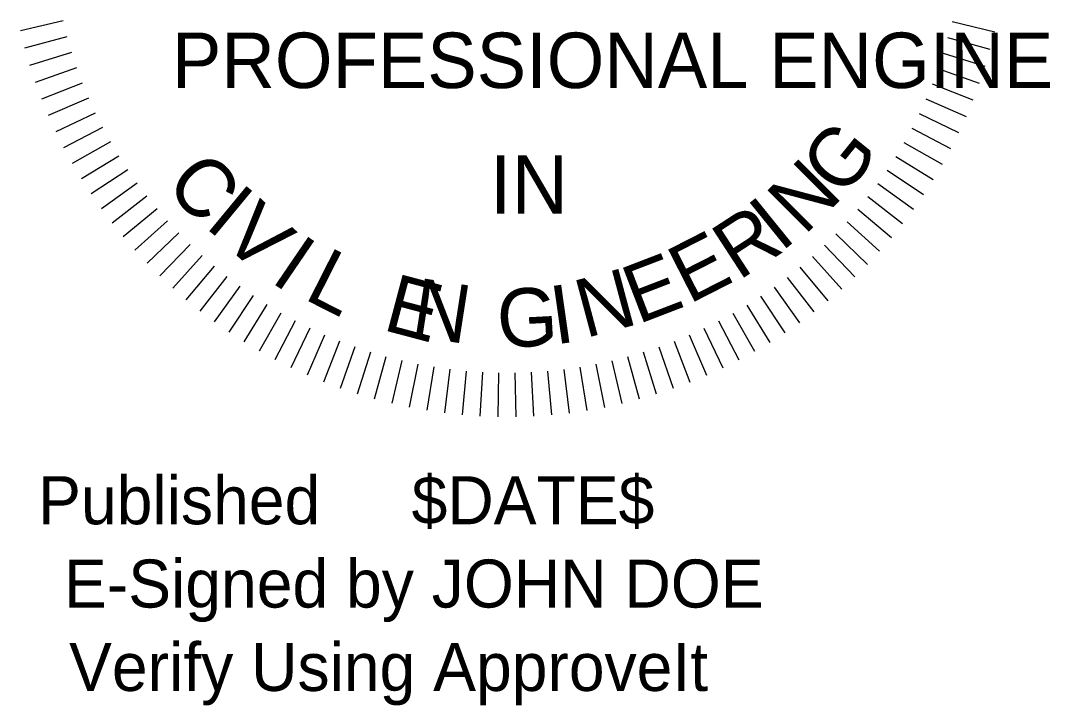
# Model space of a CAD drawing. Extents: x 0.19 to 2.82, y 0.04 to 1.79.
# Drawn here: x 2.2553 to 2.3944, y 0.7604 to 0.8531 of the extents above; entities that cross this region are included whole.
import ezdxf

# ---------------------------------------------------------------- set-up
doc = ezdxf.new("R2010")
doc.units = 0
doc.layers.add('Annotation', color=7, linetype='Continuous')
doc.layers.add('Seal', color=7, linetype='Continuous')

msp = doc.modelspace()

# ---------------------------------------------------------------- linework, layer by layer
at = {"layer": 'Seal'}
for p, q in [((2.25526, 0.85172), (2.26104, 0.85308)), ((2.38709, 0.85152), (2.38132, 0.8529)), ((2.25586, 0.84938), (2.26158, 0.85094)), ((2.38649, 0.84918), (2.38077, 0.85076)), ((2.25654, 0.84706), (2.2622, 0.84882)), ((2.38581, 0.84686), (2.38014, 0.84864)), ((2.2573, 0.84476), (2.2629, 0.84673)), ((2.38504, 0.84457), (2.37944, 0.84655)), ((2.25814, 0.8425), (2.26366, 0.84466)), ((2.38419, 0.8423), (2.37867, 0.84449)), ((2.25906, 0.84026), (2.26451, 0.84262)), ((2.38326, 0.84007), (2.37782, 0.84245)), ((2.26006, 0.83806), (2.26542, 0.84061)), ((2.38225, 0.83787), (2.3769, 0.84044)), ((2.26114, 0.8359), (2.2664, 0.83864)), ((2.38117, 0.83571), (2.37591, 0.83847)), ((2.26229, 0.83377), (2.26746, 0.8367)), ((2.38001, 0.83359), (2.37485, 0.83654)), ((2.26353, 0.83169), (2.26858, 0.8348)), ((2.37877, 0.83152), (2.37372, 0.83464)), ((2.26483, 0.82966), (2.26977, 0.83295)), ((2.37746, 0.82948), (2.37253, 0.83279)), ((2.26621, 0.82767), (2.27103, 0.83113)), ((2.37608, 0.8275), (2.37127, 0.83098)), ((2.26765, 0.82573), (2.27234, 0.82936)), ((2.37463, 0.82557), (2.36994, 0.82922)), ((2.26917, 0.82385), (2.27373, 0.82764)), ((2.37311, 0.82369), (2.36856, 0.8275)), ((2.27075, 0.82202), (2.27517, 0.82598)), ((2.37152, 0.82186), (2.36711, 0.82583)), ((2.27239, 0.82024), (2.27667, 0.82436)), ((2.36987, 0.82009), (2.3656, 0.82422)), ((2.2741, 0.81853), (2.27823, 0.8228)), ((2.36816, 0.81839), (2.36404, 0.82267)), ((2.27586, 0.81688), (2.27984, 0.82129)), ((2.36639, 0.81674), (2.36243, 0.82116)), ((2.27769, 0.81529), (2.2815, 0.81984)), ((2.36456, 0.81516), (2.36076, 0.81972)), ((2.27957, 0.81377), (2.28322, 0.81846)), ((2.36267, 0.81365), (2.35904, 0.81834)), ((2.2815, 0.81232), (2.28498, 0.81713)), ((2.36073, 0.8122), (2.35727, 0.81702)), ((2.28349, 0.81094), (2.28679, 0.81587)), ((2.35874, 0.81083), (2.35545, 0.81577)), ((2.28552, 0.80963), (2.28865, 0.81468)), ((2.35671, 0.80952), (2.3536, 0.81458)), ((2.2876, 0.80839), (2.29054, 0.81355)), ((2.28972, 0.80723), (2.29248, 0.81249)), ((2.3525, 0.80714), (2.34976, 0.8124)), ((2.35463, 0.80829), (2.3517, 0.81345)), ((2.29188, 0.80615), (2.29445, 0.8115)), ((2.35034, 0.80606), (2.34779, 0.81142)), ((2.29408, 0.80514), (2.29645, 0.81058)), ((2.29631, 0.80421), (2.29849, 0.80973)), ((2.3459, 0.80413), (2.34374, 0.80966)), ((2.34814, 0.80506), (2.34578, 0.8105)), ((2.29857, 0.80336), (2.30056, 0.80896)), ((2.30086, 0.80259), (2.30265, 0.80826)), ((2.34134, 0.80253), (2.33958, 0.8082)), ((2.34364, 0.80329), (2.34167, 0.80889)), ((2.30318, 0.80191), (2.30476, 0.80763)), ((2.30553, 0.80131), (2.3069, 0.80708)), ((2.33668, 0.80126), (2.33532, 0.80704)), ((2.33902, 0.80185), (2.33746, 0.80758)), ((2.30789, 0.80079), (2.30905, 0.80661)), ((2.31027, 0.80036), (2.31122, 0.80622)), ((2.31266, 0.80001), (2.31341, 0.8059)), ((2.31506, 0.79975), (2.3156, 0.80566)), ((2.31747, 0.79957), (2.3178, 0.8055)), ((2.31989, 0.79948), (2.32, 0.80542)), ((2.32231, 0.79948), (2.32221, 0.80541)), ((2.32472, 0.79956), (2.32442, 0.80549)), ((2.32714, 0.79973), (2.32662, 0.80564)), ((2.32954, 0.79998), (2.32881, 0.80587)), ((2.33193, 0.80032), (2.33099, 0.80619)), ((2.33431, 0.80075), (2.33316, 0.80657))]:
    msp.add_line(p, q, dxfattribs=at)

# ---------------------------------------------------------------- texts
at = {"layer": 'Annotation'}
for s, p in [('Published', (2.25764, 0.78493)), ('$DATE$', (2.30818, 0.78493)), ('E-Signed by JOHN DOE', (2.26114, 0.77366)), ('Verify Using ApproveIt', (2.26183, 0.76238))]:
    msp.add_text(s, height=0.0065, dxfattribs=at).set_placement(p)
at = {"layer": 'Seal'}
for s, height, p in [('PROFESSIONAL ENGINEER', 0.0075, (2.27575, 0.84395)), ('IN', 0.0079, (2.31877, 0.82696))]:
    msp.add_text(s, height=height, dxfattribs=at).set_placement(p)
for s, rotation, p in [('G', 51.0008, (2.36652, 0.82896)), ('C', 312.2219, (2.27463, 0.83074)), ('N', 45.0007, (2.36131, 0.8239)), ('I', 320.3933, (2.28005, 0.82521)), ('V', 317.5713, (2.28228, 0.82333)), ('I', 39.0007, (2.35816, 0.82168)), ('R', 33.0007, (2.35244, 0.81783)), ('I', 325.7176, (2.28893, 0.81783)), ('E', 27.0007, (2.34572, 0.81466)), ('L', 333.1234, (2.29344, 0.8155)), ('E', 21.0007, (2.33881, 0.81195)), ('N', 15.0007, (2.33167, 0.81009)), ('E', 345.1234, (2.3041, 0.81127)), ('N', 171.1218, (2.31667, 0.81712)), ('G', 3.0006, (2.31993, 0.80877)), ('I', 8.073, (2.32759, 0.80924))]:
    msp.add_text(s, height=0.0079, rotation=rotation, dxfattribs=at).set_placement(p)

doc.saveas('drawing.dxf')
